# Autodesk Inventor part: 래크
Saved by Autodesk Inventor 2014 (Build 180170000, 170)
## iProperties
Created: 2024-11
Part Number: 래크
Material: 일반
Document SubType Name: Modeling
Designer: dg
Density: 1 g/cm^3
Appearance: 기본값
Author: dg
Author: jhkim
Creation Date: 2024-10-25
Sending System: Autodesk Inventor 2025
Preprocessor: ST-DEVELOPER v20
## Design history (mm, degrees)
node "래크1"
node "솔리드1"
node "기준1"
